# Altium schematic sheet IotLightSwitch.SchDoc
size A4
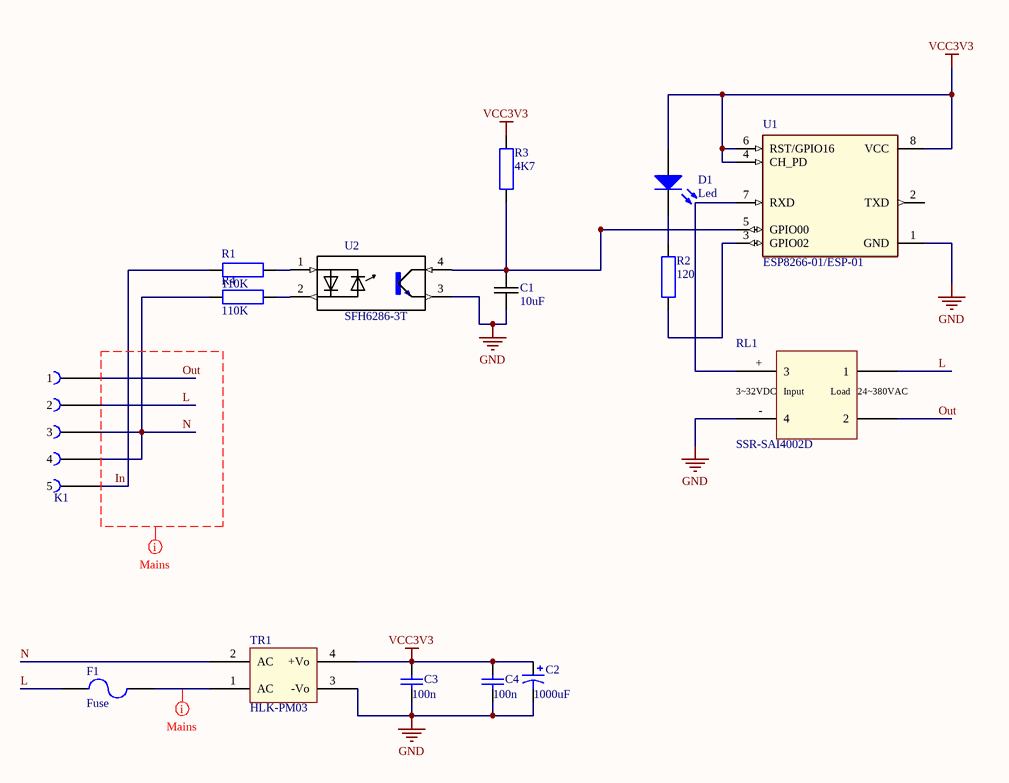
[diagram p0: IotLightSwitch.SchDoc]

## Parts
C1  10uF  [0805C-GENERIC]
C2  value 1000uF  [X]  (hidden comment: T491X)
C3  value 100n  [1608[0603]]  (hidden comment: Cap Semi)
C4  value 100n  [1608[0603]]  (hidden comment: Cap Semi)
D1  Led  [LED1608]
F1  Fuse  [SmdFuse1808]
K1  ScrewTerminal5x5.00mm  [ScrewTerminal5x5.00]  (value not drawn)
R1  value 110K  [RES1210]  (hidden comment: Resistor)
R2  value 120  [RES0603R]  (hidden comment: Resistor)
R3  value 4K7  [RES0603R]  (hidden comment: Resistor)
R4  value 110K  [RES1210]  (hidden comment: Resistor)
RL1  SSR-SAI4002D  [SAI4002D]
TR1  HLK-PM03  [HLK-PM03]
U1  ESP8266-01/ESP-01  [XCVR_ESP8266-01/ESP-01]
U2  SFH6286-3T  [SOIC254P977X460-4N]

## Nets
GND: C1.2 C2.2 C3.1 C4.1 RL1.-(4) TR1.3(-Vo) U1.1(GND) U2.3
VCC3V3: C2.1 C3.2 C4.2 D1.1(A) R3.1 TR1.4(+Vo) U1.4(CH_PD) U1.6(RST/GPIO16) U1.8(VCC)
In: K1.5 R1.1
L: F1.1 K1.2 RL1.1
N: K1.3 K1.4 R4.1 TR1.2(AC)
Out: K1.1 RL1.2
NetC1_1: C1.1 R3.2 U1.5(GPIO00) U2.4
NetD1_2: D1.2(K) R2.1
NetF1_2: F1.2 TR1.1(AC)
NetR1_2: R1.2 U2.1
NetR2_2: R2.2 U1.3(GPIO02)
NetR4_2: R4.2 U2.2
NetRL1_+: RL1.+(3) U1.7(RXD)

Not connected (* = marked no-connect by the designer): U1 2(TXD)

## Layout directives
net class Undefined; rule Clearance Constraint [Clearance = 2mm]; rule Width Constraint [Pref Width = 2mm    Min Width = 1mm    Max Width = 3mm]: In, L, N, NetF1_2, Out

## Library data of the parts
C1 = 0805C-10UF-16V-X5R-TDK: CAPACITOR 0805 CERAMIC; Manufacturer Part Number: C2012X5R1C106M; Manufacturer: TDK Corporation; REEL: C63
C2 = T491X: Solid Tantalum Chip Capacitor, Standard T491 Series - Industrial Grade; PCB_Layout: Round Glue Pad at 2.9 ±0.1mm in diameter at KEMET's option
C3 C4 = Cap Semi: Capacitor (Semiconductor SIM Model)
D1 = Led: pin to pad: 1>A 2>K
RL1 = SSR-SAI4002D: pin to pad: +>3 ->4
TR1 = HLK-PM03: Hi-Link HLK-PM03 3.3VDC/3W Power Module
U2 = SFH6286-3T: SFH6286 Series 5300 Vrms 55 V Phototransistor Output Optocoupler - SMD-4; MF: Vishay Semiconductor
